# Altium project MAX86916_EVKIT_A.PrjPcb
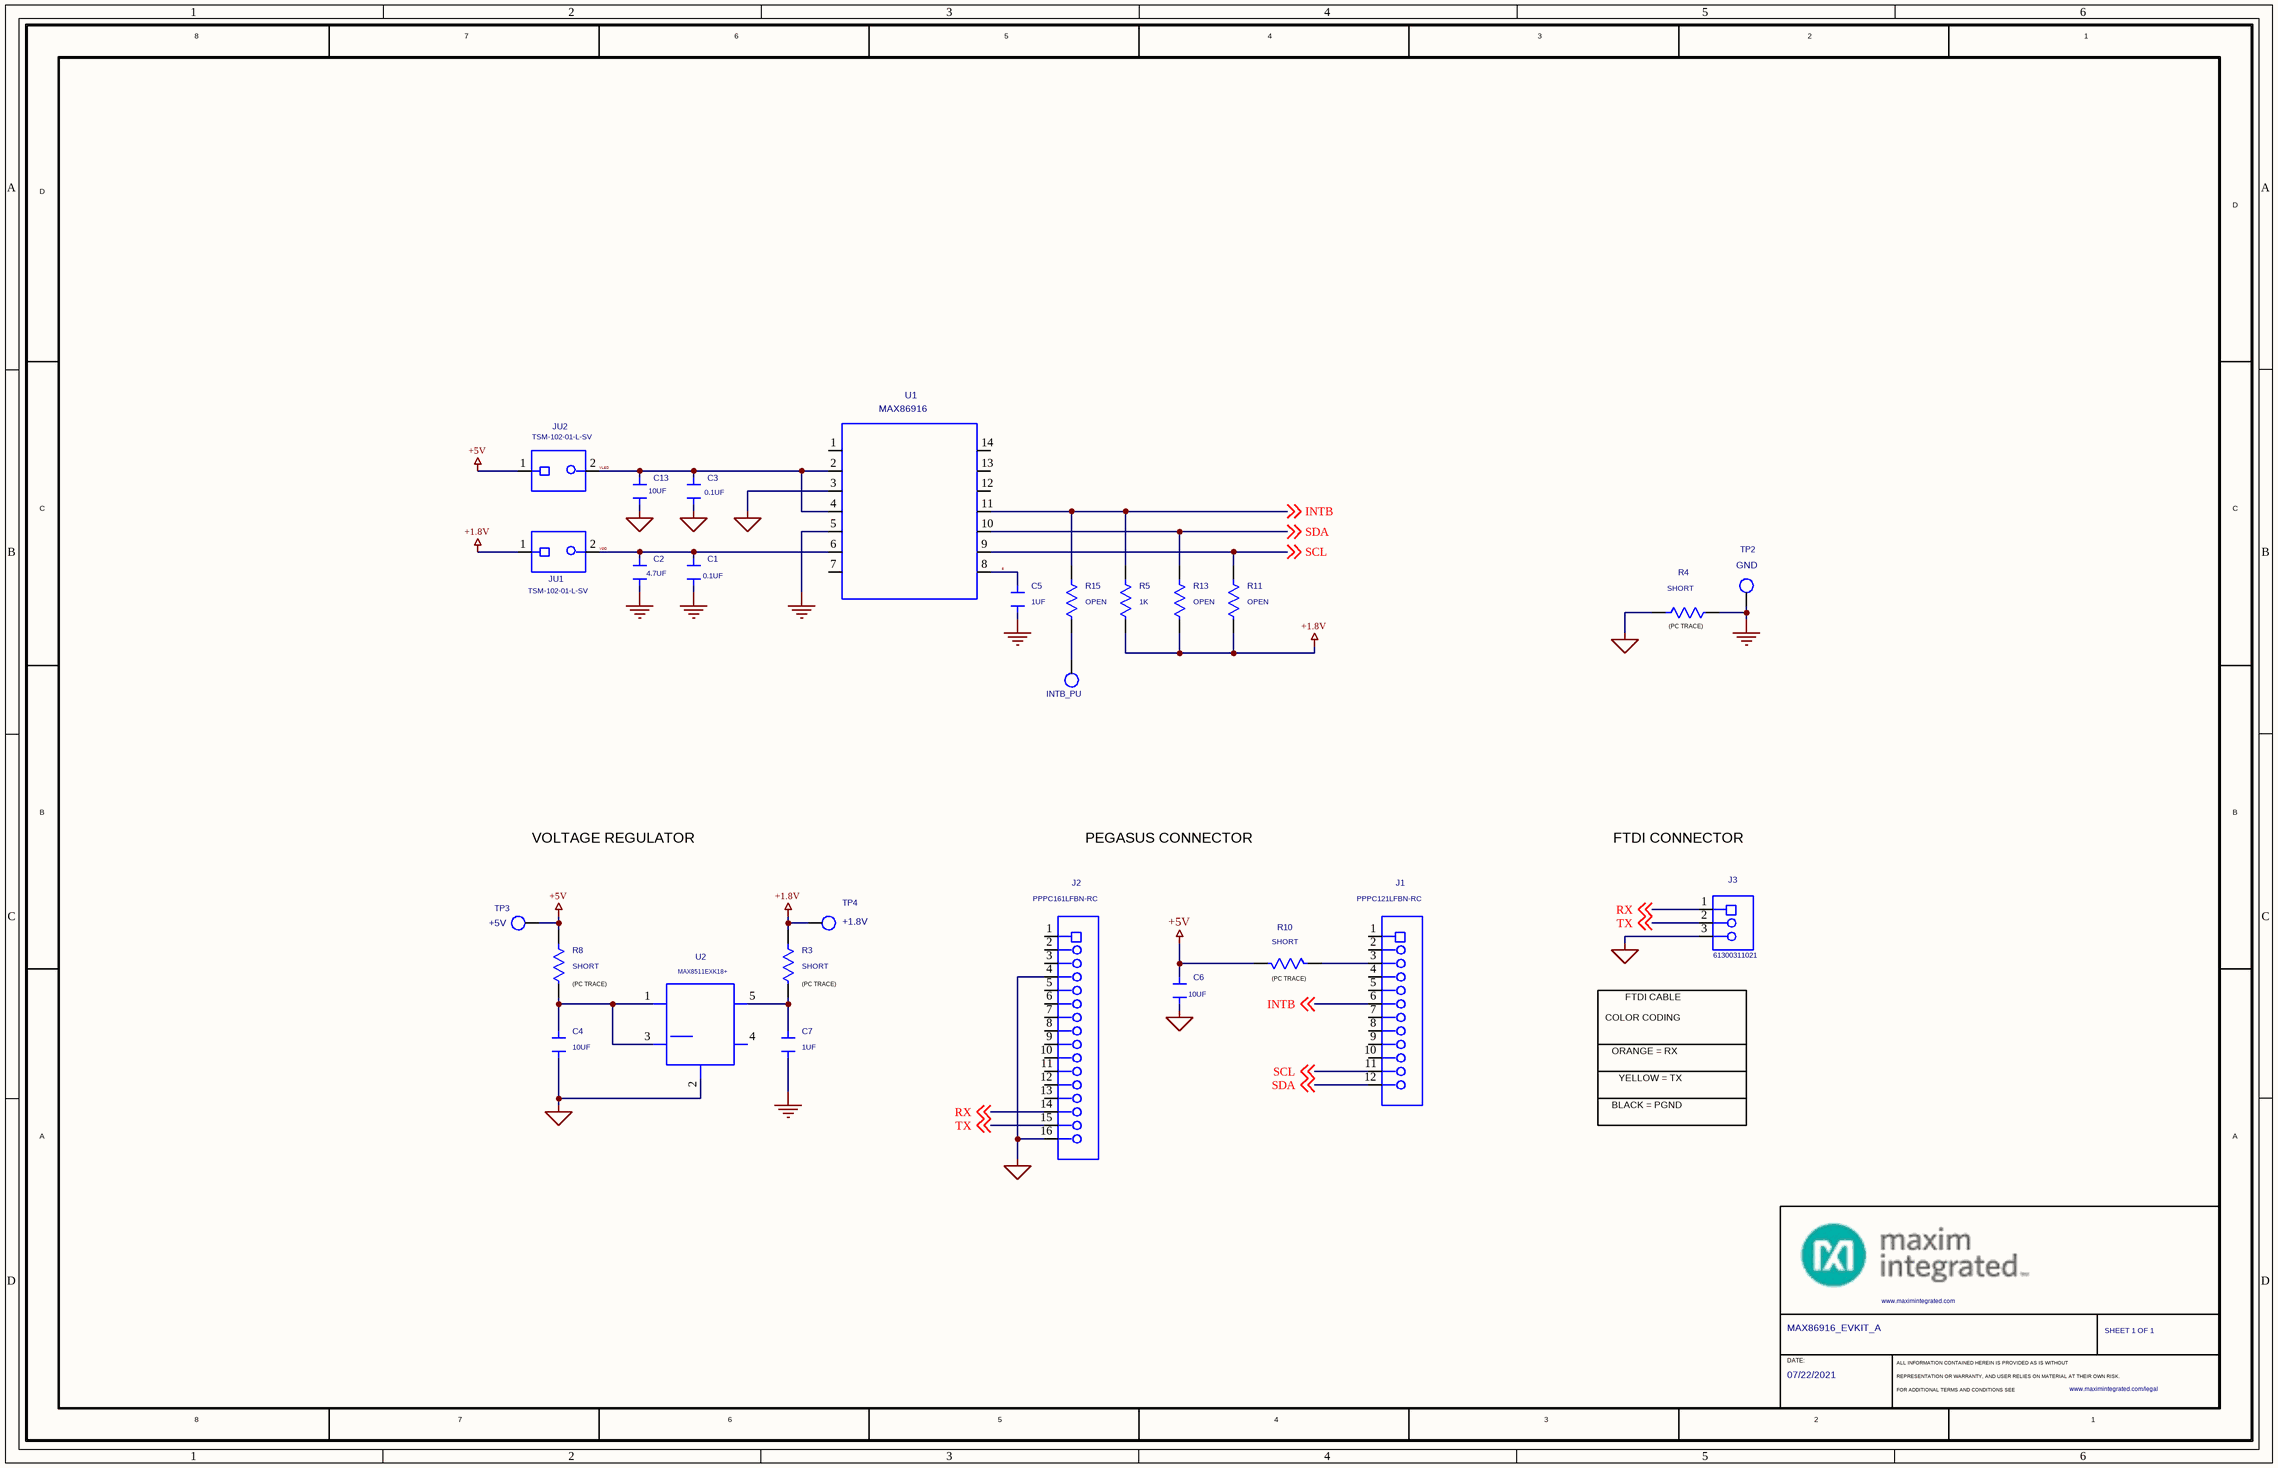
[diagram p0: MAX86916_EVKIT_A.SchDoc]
1 sheet, 28 parts. Net scope: global (net labels, ports and power ports of the same name join across sheets).

## Sheet MAX86916_EVKIT_A.SchDoc
size 426 x 274 mm

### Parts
*  CUSTOM_TXT_CDS21: SHEET 1 OF 1  PROJECT_TITLE: MAX86916_EVKIT_A  DATE: 07/22/2021  (hidden comment: MAXIM_B_SIZE_CF)  (graphical)
C1  0.1UF  [0402]
C2  4.7UF  [0402]
C3  0.1UF  [0402]
C4  10UF  [0603]
C5  1UF  [0402]
C6  10UF  [0603]
C7  1UF  [0402]
C13  10UF  [0402]
INTB_PU  N/A  [KEYS_5004]  (value not drawn)
J1  PPPC121LFBN-RC  [SULLINS_XPXC121LFBN]
J2  PPPC161LFBN-RC  [SULLINS_XPXC161LFBN]
J3  61300311021  [WE_61300311021]
JU1  TSM-102-01-L-SV  [SAMTEC_TSM-102-01-L-SV]
JU2  TSM-102-01-L-SV  [SAMTEC_TSM-102-01-L-SV]
R3  SHORT  [0603_SHORT]
R4  SHORT  [0402_SHORT]
R5  1K  [0402]
R8  SHORT  [0603_SHORT]
R10  SHORT  [0603_SHORT]
R11  OPEN  [0402]
R13  OPEN  [0402]
R15  OPEN  [0402]
TP2  LABEL: GND  [TP_C127]  (hidden comment: N/A)
TP3  LABEL: +5V  [KEYS_5000]  (hidden comment: N/A)
TP4  LABEL: +1.8V  [TP_C127]  (hidden comment: N/A)
U1  MAX86916  [MAXIM_90-100122]
U2  MAX8511EXK18+  [MAXIM_90-0188]

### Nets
+1.8V: JU1.1 R3.1 R5.2 R11.2 R13.2 TP4.1(TP1)
+5V: C6.2 JU2.1 R8.1 R10.2 TP3.1(TP1)
AGND: C1.1 C2.1 C5.1 C7.1 R4.2 TP2.1(TP1) U1.5
PGND: C3.1 C4.1 C6.1 C13.1 J2.4 J2.16 J3.3 R4.1 U1.3 U2.2(GND)
8: C5.2 U1.8
INTB: J1.6 R5.1 R15.1 U1.11 ; off-sheet INTB
RX: J2.14 J3.1 ; off-sheet RX
SCL: J1.11 R11.1 U1.9 ; off-sheet SCL
SDA: J1.12 R13.1 U1.10 ; off-sheet SDA
TX: J2.15 J3.2 ; off-sheet TX
VDD: C1.2 C2.2 JU1.2 U1.6
VLED: C3.2 C13.2 JU2.2 U1.2 U1.4
NetC4_2: C4.2 R8.2 U2.1(IN) U2.3(SHDN*)
NetC7_2: C7.2 R3.2 U2.5(OUT)
NetINTB_PU_1: INTB_PU.1(TP1) R15.2
NetJ1_3: J1.3 R10.1

Not connected (* = marked no-connect by the designer): J1 1 2 4 5 7 8 9 10; J2 1 2 3 5 6 7 8 9 10 11 12 13; U1 1 7 12 13 14; U2 4(NC)

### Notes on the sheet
- (near R4) (PC TRACE)
- VOLTAGE REGULATOR
- PEGASUS CONNECTOR
- FTDI CONNECTOR
- (near R8) (PC TRACE)
- (near R3) (PC TRACE)
- (near R10) (PC TRACE)
- FTDI CABLE
- COLOR CODING
- ORANGE = RX
- YELLOW = TX
- BLACK = PGND

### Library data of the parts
* = MAXIM_B_SIZE_CF: OriginalSymbolOrigin: (175,5230); COMMENT_BODY: TRUE; Page Number: 1; CURRENT_DESIGN_SHEET: Page_1
C1 C3 = CAP_NP: CAP; SMT (0402); 0.1UF; 10%; 50V; X7R; CERAMIC; MFG_PART_NUMBER: CGA2B3X7R1H104K; C1005X7R1H104K050BB; GRM155R71H104KE14; MANUFACTURER: TDK;MURATA;TDK;TAIYO YUDEN; OriginalSymbolOrigin: (-50,50); PACK_TYPE: 0402CAP; MAXINV: 20-000U1-04A; CAP: 1.00E-07; DRAWING: @MAX86916_EVKIT_A_LIB.MAX86916_EVKIT_A(SCH_1):PAGE1; PHYS_PAGE: 2; ROOM: U1; TEMP_RANGE: -55 DEGC TO +125 DEGC; VLOG_PARAM01: CAP:INTEGER
C2 = CAP_NP: CAP; SMT (0402); 4.7UF; 20%; 16V; X5R; CERAMIC; MFG_PART_NUMBER: CL05A475MO5NUN; MANUFACTURER: SAMSUNG ELECTRO-MECHANICS; OriginalSymbolOrigin: (-50,50); PACK_TYPE: 0402CAP; MAXINV: 20-004U7-33B; CAP: 4.70E-06; DRAWING: @MAX86916_EVKIT_A_LIB.MAX86916_EVKIT_A(SCH_1):PAGE1; PHYS_PAGE: 2; ROOM: U1; TEMP_RANGE: -55 DEGC TO +85 DEGC; VLOG_PARAM01: CAP:INTEGER; MATERIAL_TYPE: CERAMIC CHIP
C4 = CAP_NP: CAP; SMT (0603); 10UF; 20%; 16V; X5R; CERAMIC; MFG_PART_NUMBER: GRM188R61C106MA73; MANUFACTURER: MURATA; OriginalSymbolOrigin: (-50,50); PACK_TYPE: 0603CAP; MAXINV: 20-0010U-A29; CAP: 1.00E-05; DRAWING: @MAX86916_EVKIT_A_LIB.MAX86916_EVKIT_A(SCH_1):PAGE1; PHYS_PAGE: 2; TEMP_RANGE: -55 DEGC TO +85 DEGC; VLOG_PARAM01: CAP:INTEGER; MATERIAL_TYPE: CERAMIC CHIP
C5 = CAP_NP: CAP; SMT (0402); 1UF; 10%; 16V; X5R; CERAMIC; MFG_PART_NUMBER: CL05A105KO5NNN; MANUFACTURER: SAMSUNG; OriginalSymbolOrigin: (-50,50); PACK_TYPE: 0402CAP; MAXINV: EC2430; CAP: 1.00E-06; DRAWING: @MAX86916_EVKIT_A_LIB.MAX86916_EVKIT_A(SCH_1):PAGE1; PHYS_PAGE: 2; TEMP_RANGE: -55 DEGC TO +85 DEGC; VLOG_PARAM01: CAP:INTEGER; MATERIAL_TYPE: CERAMIC CHIP
C6 = CAP_NP: CAP; SMT (0603); 10UF; 20%; 16V; X5R; CERAMIC; MFG_PART_NUMBER: GRM188R61C106MA73; MANUFACTURER: MURATA; OriginalSymbolOrigin: (-50,50); PACK_TYPE: 0603CAP; MAXINV: 20-0010U-A29; CAP: 1.00E-05; DRAWING: @MAX86916_EVKIT_A_LIB.MAX86916_EVKIT_A(SCH_1):PAGE1; PHYS_PAGE: 2; TEMP_RANGE: -55 DEGC TO +85 DEGC; MATERIAL_TYPE: CERAMIC CHIP; VLOG_PARAM01: CAP:INTEGER
C7 = CAP_NP: CAP; SMT (0402); 1UF; 10%; 16V; X5R; CERAMIC; MFG_PART_NUMBER: CL05A105KO5NNN; MANUFACTURER: SAMSUNG; OriginalSymbolOrigin: (-50,50); PACK_TYPE: 0402CAP; MAXINV: EC2430; CAP: 1.00E-06; DRAWING: @MAX86916_EVKIT_A_LIB.MAX86916_EVKIT_A(SCH_1):PAGE1; PHYS_PAGE: 2; TEMP_RANGE: -55 DEGC TO +85 DEGC; VLOG_PARAM01: CAP:INTEGER
C13 = CAP_NP: CAP; SMT (0402); 10UF; 20%; 10V; X5R; CERAMIC; MFG_PART_NUMBER: GRM155R61A106ME44; GRM155R61A106ME11; 0402ZD106MAT2A; MANUFACTURER: MURATA;MURATA;AVX;SAMSUNG; OriginalSymbolOrigin: (-50,50); PACK_TYPE: 0402CAP; MAXINV: 20-0010U-BA12; CAP: 1.00E-05; DRAWING: @MAX86916_EVKIT_A_LIB.MAX86916_EVKIT_A(SCH_1):PAGE1; PHYS_PAGE: 2; ROOM: U1; TEMP_RANGE: -55 DEGC TO +85 DEGC; VLOG_PARAM01: CAP:INTEGER; MATERIAL_TYPE: CERAMIC CHIP
INTB_PU = TP: TEST POINT; PIN DIA=0.1IN; TOTAL LENGTH=0.3IN; BOARD HOLE=0.04IN; YELLOW; PHOSPHOR BRONZE WIRE SILVER PLATE FINISH; RECOMMENDED FOR BOARD THICKNESS=0.062IN; NOT FOR COLD TEST; MFG_PART_NUMBER: 5004; MANUFACTURER: KEYSTONE; OriginalSymbolOrigin: (-125,50); MAXINV: 02-TPMINI5004-00; DRAWING: @MAX86916_EVKIT_A_LIB.MAX86916_EVKIT_A(SCH_1):PAGE1; PHYS_PAGE: 2; VER: 1
J1 = HEADER_12P: CONNECTOR; FEMALE; THROUGH HOLE; HEADER FEMALE; STRAIGHT; 12PINS; MANUFACTURER: SULLINS ELECTRONICS CORP; OriginalSymbolOrigin: (-75,375); PACK_TYPE: TH; MAXINV: 01-PPPC121LFBN12P-19; DRAWING: @MAX86916_EVKIT_A_LIB.MAX86916_EVKIT_A(SCH_1):PAGE1; PHYS_PAGE: 2; VER: 1; VOLTAGE_RATING: 250V; TEMP_RANGE: -40 DEGC TO +105 DEGC
J2 = HEADER_16P: CONNECTOR; FEMALE; THROUGH HOLE; LFB SERIES; 2.54MM CONTACT CENTER; STRAIGHT; 16PINS; MANUFACTURER: SULLINS ELECTRONICS CORP.; OriginalSymbolOrigin: (-75,475); PACK_TYPE: SIP; MAXINV: 01-PPPC161LFBN16P-19; DRAWING: @MAX86916_EVKIT_A_LIB.MAX86916_EVKIT_A(SCH_1):PAGE1; PHYS_PAGE: 2; VER: 1; TEMP_RANGE: -40 DEGC TO +105 DEGC
J3 = HEADER_3P: CONNECTOR; MALE; THROUGH HOLE; 2.54MM THT ANGLED PIN HEADER; RIGHT ANGLE; 3PINS; MANUFACTURER: WURTH ELECTRONICS INC; OriginalSymbolOrigin: (-75,100); PACK_TYPE: RA; MAXINV: 01-613003110213P-19; DRAWING: @MAX86916_EVKIT_A_LIB.MAX86916_EVKIT_A(SCH_1):PAGE1; PHYS_PAGE: 2; VER: 1; VOLTAGE_RATING: 250V; TEMP_RANGE: -40 DEGC TO +105 DEGC
JU1 JU2 = HEADER_2P: CONNECTOR; MALE; SMT; SINGLE ROW; STRAIGHT THROUGH; 2PINS; MANUFACTURER: SAMTEC; OriginalSymbolOrigin: (-100,100); PACK_TYPE: SIP; MAXINV: 01-TSM10201LSV2P-17; DRAWING: @MAX86916_EVKIT_A_LIB.MAX86916_EVKIT_A(SCH_1):PAGE1; PHYS_PAGE: 2; TEMP_RANGE: -55 DEGC TO +125 DEGC
R3 R8 = EVK_GENERIC_RESISTORS: PACKAGE OUTLINE 0603 RESISTOR - EVKIT; OriginalSymbolOrigin: (-50,75); DRAWING: @MAX86916_EVKIT_A_LIB.MAX86916_EVKIT_A(SCH_1):PAGE1; PHYS_PAGE: 2; ROOM: U1; VER: 4
R4 = EVK_GENERIC_RESISTORS: PACKAGE OUTLINE 0402 RESISTOR - EVKIT; OriginalSymbolOrigin: (-50,75); DRAWING: @MAX86916_EVKIT_A_LIB.MAX86916_EVKIT_A(SCH_1):PAGE1; PHYS_PAGE: 2; ROOM: U1; VER: 4
R5 = RES_SMD: RES; SMT (0402); 1K; 1%; +/-100PPM/DEGC; 0.1000W; MFG_PART_NUMBER: ERJ-2RKF1001; MANUFACTURER: PANASONIC; OriginalSymbolOrigin: (-50,75); PACK_TYPE: 0402RES; MAXINV: 80-0001K-18; DRAWING: @MAX86916_EVKIT_A_LIB.MAX86916_EVKIT_A(SCH_1):PAGE1; PHYS_PAGE: 2; POWER_RATING: 0.10W; RES: 1.00E03; ROOM: U1; VER: 4; TEMP_RANGE: -55 DEGC TO +155 DEGC; MATERIAL_TYPE: THICK FILM; VLOG_PARAM01: RES:INTEGER
R10 = EVK_GENERIC_RESISTORS#1: PACKAGE OUTLINE 0603 RESISTOR - EVKIT; OriginalSymbolOrigin: (-75,50); DRAWING: @MAX86916_EVKIT_A_LIB.MAX86916_EVKIT_A(SCH_1):PAGE1; PHYS_PAGE: 2; ROOM: U1
R11 R13 R15 = EVK_GENERIC_RESISTORS: PACKAGE OUTLINE 0402 RESISTOR - EVKIT; OriginalSymbolOrigin: (-50,75); DRAWING: @MAX86916_EVKIT_A_LIB.MAX86916_EVKIT_A(SCH_1):PAGE1; PHYS_PAGE: 2; VER: 4
TP2 TP4 = TP: TESTPOINT WITH 1.27MM PAD DIAMETER; OriginalSymbolOrigin: (-125,50); DRAWING: @MAX86916_EVKIT_A_LIB.MAX86916_EVKIT_A(SCH_1):PAGE1; PHYS_PAGE: 2; VER: 1
TP3 = TP: TEST POINT; PIN DIA=0.1IN; TOTAL LENGTH=0.3IN; BOARD HOLE=0.04IN; RED; PHOSPHOR BRONZE WIRE SILVER PLATE FINISH; RECOMMENDED FOR BOARD THICKNESS=0.062IN; NOT FOR COLD TEST; MFG_PART_NUMBER: 5000; MANUFACTURER: KEYSTONE; OriginalSymbolOrigin: (-125,50); MAXINV: 02-TPMINI5000-00; DRAWING: @MAX86916_EVKIT_A_LIB.MAX86916_EVKIT_A(SCH_1):PAGE1; PHYS_PAGE: 2; VER: 1
U1 = EK_MAX86916: EVKIT PART - IC; MAX86916; OLGA14; PACKAGE DRAWING NUMBER: 21-100325; LAND PATTERN NUMBER: 90-100122; PACKAGE CODE: F143H7MK+1; MANUFACTURER: MAXIM; OriginalSymbolOrigin: (-250,325); DRAWING: @MAX86916_EVKIT_A_LIB.MAX86916_EVKIT_A(SCH_1):PAGE1; PHYS_PAGE: 2; VER: 1
U2 = MAX8511: IC; VREG; ULTRA-LOW-NOISE; HIGH PSRR; LOW=DROPOUT; LINEAR REGULATOR; SC70-5; MANUFACTURER: MAXIM; OriginalSymbolOrigin: (-175,175); PACK_TYPE: SC70; MAXINV: 10-MAX8511EXK18-X; CLASSIFICATION: VOLTAGE REGULATOR; DRAWING: @MAX86916_EVKIT_A_LIB.MAX86916_EVKIT_A(SCH_1):PAGE1; PHYS_PAGE: 2; VER: 1; VOLTAGE_RATING: 1.8V; TEMP_RANGE: -40 DEGC TO +85 DEGC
